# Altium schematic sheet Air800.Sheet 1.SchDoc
size 431 x 279 mm
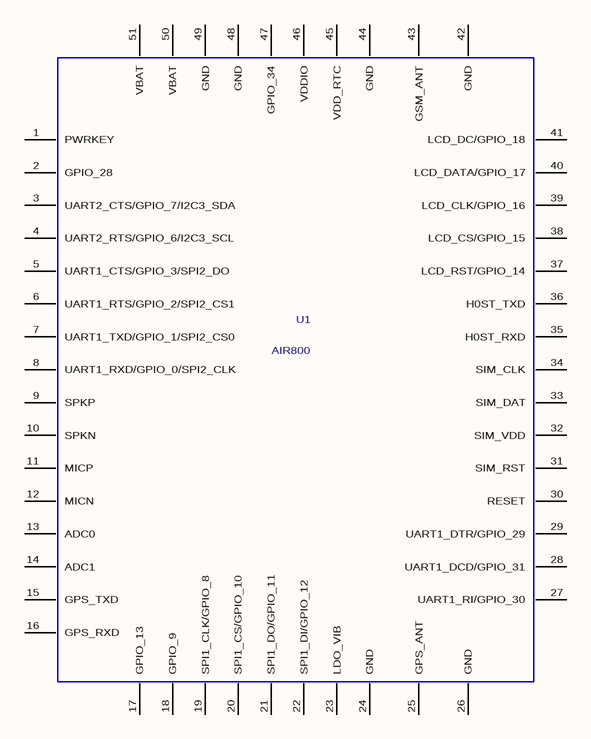
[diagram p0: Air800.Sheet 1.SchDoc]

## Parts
U1  AIR800  [AIR800]

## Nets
GND: U1.52(GND) U1.53(GND) U1.54(GND)

Not connected (* = marked no-connect by the designer): U1 1(PWRKEY) 2(GPIO_28) 3(UART2_CTS/GPIO_7/I2C3_SDA) 4(UART2_RTS/GPIO_6/I2C3_SCL) 5(UART1_CTS/GPIO_3/SPI2_DO) 6(UART1_RTS/GPIO_2/SPI2_CS1) 7(UART1_TXD/GPIO_1/SPI2_CS0) 8(UART1_RXD/GPIO_0/SPI2_CLK) 9(SPKP) 10(SPKN) 11(MICP) 12(MICN) 13(ADC0) 14(ADC1) 15(GPS_TXD) 16(GPS_RXD) 17(GPIO_13) 18(GPIO_9) 19(SPI1_CLK/GPIO_8) 20(SPI1_CS/GPIO_10) 21(SPI1_DO/GPIO_11) 22(SPI1_DI/GPIO_12) 23(LDO_VIB) 24(GND) 25(GPS_ANT) 26(GND) 27(UART1_RI/GPIO_30) 28(UART1_DCD/GPIO_31) 29(UART1_DTR/GPIO_29) 30(RESET) 31(SIM_RST) 32(SIM_VDD) 33(SIM_DAT) 34(SIM_CLK) 35(H0ST_RXD) 36(H0ST_TXD) 37(LCD_RST/GPIO_14) 38(LCD_CS/GPIO_15) 39(LCD_CLK/GPIO_16) 40(LCD_DATA/GPIO_17) 41(LCD_DC/GPIO_18) 42(GND) 43(GSM_ANT) 44(GND) 45(VDD_RTC) 46(VDDIO) 47(GPIO_34) 48(GND) 49(GND) 50(VBAT) 51(VBAT)

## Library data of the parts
U1 = AIR800: Geometry.Height: 2.3 MM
